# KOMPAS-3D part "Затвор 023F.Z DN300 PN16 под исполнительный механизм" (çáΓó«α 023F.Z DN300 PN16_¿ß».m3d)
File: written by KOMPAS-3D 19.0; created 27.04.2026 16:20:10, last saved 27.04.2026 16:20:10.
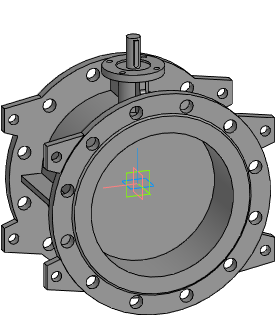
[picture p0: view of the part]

Document properties: Автор: Евгений; Полное имя файла: Z:\3.Личные\kachalov\3d для проектировщиков\1.7 Тип 023F.Z Затвор дисковый поворотный фланцевый с двумя эксцентриками\Затвор 023F.Z DN200-DN1600_исп\_stp_Затвор 023F.Z DN200-DN1600_исп\Затвор 023F.Z DN300 PN16_исп.m3d

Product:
- Part/product: Затвор 023F.Z DN300 PN16 под исполнительный механизм

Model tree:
1. Операция без истории:1  (labels: Затвор 023F.Z DN300 PN16 под исполнительный механизм)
